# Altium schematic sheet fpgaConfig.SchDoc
size A; SheetNumber: 2; SheetTotal: 2
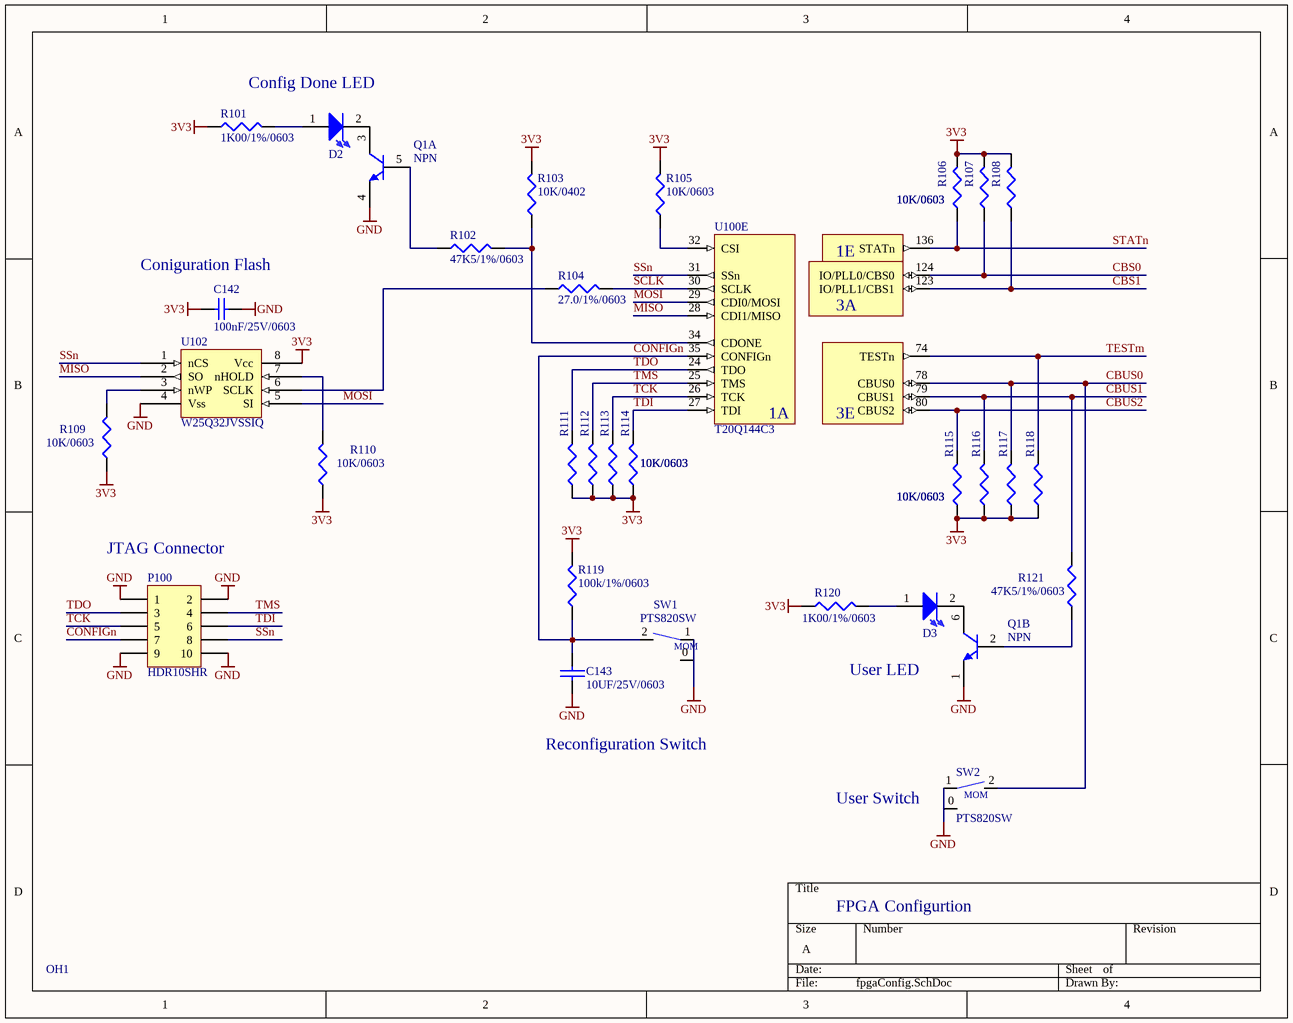
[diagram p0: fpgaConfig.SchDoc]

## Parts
C142  100nF/25V/0603  [MY0603]
C143  10UF/25V/0603  [MY0603]
D2  LTST-C191KGKT  [LED0603]  (value not drawn)
D3  LTST-C191KGKT  [LED0603]  (value not drawn)
OH1  OPENHW_SCH  (value not drawn)
P100  HDR10SHR  [HDR10]
Q1  NPN  [SC70-6_HAND]  (parts A,B of 2)
R101  1K00/1%/0603  [0603]
R102  47K5/1%/0603  [0603]
R103  10K/0402  [0402]
R104  27.0/1%/0603  [0603]
R105  10K/0603  [0603]
R106  10K/0603  [0603]
R107  10K/0603  [0603]
R108  10K/0603  [0603]
R109  10K/0603  [0603]
R110  10K/0603  [0603]
R111  10K/0603  [0603]
R112  10K/0603  [0603]
R113  10K/0603  [0603]
R114  10K/0603  [0603]
R115  10K/0603  [0603]
R116  10K/0603  [0603]
R117  10K/0603  [0603]
R118  10K/0603  [0603]
R119  100k/1%/0603  [0603]
R120  1K00/1%/0603  [0603]
R121  47K5/1%/0603  [0603]
SW1  PTS820SW  [PTS820]
SW2  PTS820SW  [PTS820]
U100  T20Q144C3  [LQFP144]  (part E of 6)
U102  W25Q32JVSSIQ  [so8w]

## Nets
3V3: C142.2 R101.1 R103.2 R105.2 R106.2 R107.2 R108.2 R109.1 R110.1 R111.1 R112.1 R113.1 R114.1 R115.1 R116.1 R117.1 R118.1 R119.2 R120.1 U102.8(Vcc)
GND: C142.1 C143.2 P100.1 P100.2 P100.9 P100.10 Q1.1 Q1.4 SW1.1 SW2.1 U102.4(Vss)
CBS0: R107.1 U100.124(IO/PLL0/CBS0)
CBS1: R108.1 U100.123(IO/PLL1/CBS1)
CBUS0: R117.2 SW2.2 U100.78(CBUS0)
CBUS1: R116.2 R121.2 U100.79(CBUS1)
CBUS2: R115.2 U100.80(CBUS2)
CONFIGn: C143.1 P100.7 R119.1 SW1.2 U100.35(CONFIGn)
MISO: U100.28(CDI1/MISO) U102.2(SO)
MOSI: U100.29(CDI0/MOSI) U102.5(SI)
SCLK: R104.2 U100.30(SCLK)
SSn: P100.8 U100.31(SSn) U102.1(nCS)
STATn: R106.1 U100.136(STATn)
TCK: P100.5 R113.2 U100.26(TCK)
TDI: P100.6 R114.2 U100.27(TDI)
TDO: P100.3 R111.2 U100.24(TDO)
TESTm: R118.2 U100.74(TESTn)
TMS: P100.4 R112.2 U100.25(TMS)
NetD2_1: D2.1(A) R101.2
NetD2_2: D2.2(K) Q1.3
NetD3_1: D3.1(A) R120.2
NetD3_2: D3.2(K) Q1.6
NetQ1_2: Q1.2 R121.1
NetQ1_5: Q1.5 R102.1
NetR102_2: R102.2 R103.1 U100.34(CDONE)
NetR104_1: R104.1 U102.6(SCLK)
NetR105_1: R105.1 U100.32(CSI)
NetR109_2: R109.2 U102.3(nWP)
NetR110_2: R110.2 U102.7(nHOLD)

Not connected (* = marked no-connect by the designer): SW1 0; SW2 0

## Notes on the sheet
- Config Done LED
- (near C142) Coniguration Flash
- (near P100) JTAG Connector
- User LED
- Reconfiguration Switch
- (near SW2) User Switch
- FPGA Configurtion

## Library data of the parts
C142 = CAP100NF25V: 0.1µF ±10% 25V Ceramic Capacitor X7R 0603 (1608 Metric); MFG PN: 06033C104KAT2A; DK PN: 478-3714-1-ND; MFG: AVX
C143 = 10UF/25V/0603: 10 µF ±20% 25V Ceramic Capacitor X5R 0603 (1608 Metric); MFG: Samsung; MFG PN: CL10A106MA8NRNC; DK PN: 1276-1869-1-ND
D2 D3 = LTST-C191KGKT: Green 571nm LED Indication - Discrete 2V 0603 (1608 Metric); DK PN: 160-1446-1-ND; MFG: Liteon
P100 = HDR10SHR: Connector Header Through Hole 10 position 0.100" (2.54mm); MFG: On Shore; MFG PN: 302-S101; DK PN: ED1543-ND
Q1 = MBT3904DW1T1G: Bipolar (BJT) Transistor Array 2 NPN (Dual) 40V 200mA 300MHz 150mW Surface Mount SC-88/SC70-6/SOT-363; MFG: On Semi; DK PN: MBT3904DW1T1GOSCT-ND
R101 R120 = 1K00/1%/0603: 1 kOhms ±1% 0.1W, 1/10W Chip Resistor 0603 (1608 Metric) Moisture Resistant Thick Film; MFG: Yeago; MFG PN: RC0603FR-071KL; DK PN: 311-1.00KHRCT-ND
R102 R121 = 47K5/1%/0603: 47.5 kOhms ±1% 0.1W, 1/10W Chip Resistor 0603 (1608 Metric) Moisture Resistant Thick Film; MFG: Yeago; MFG PN: RC0603FR-0747K5L; DK PN: 311-47.5KHRCT-ND
R103 = 10K/0402: 10 kOhms ±1% 0.063W, 1/16W Chip Resistor 0402 (1005 Metric) Automotive AEC-Q200, Moisture Resistant Thick Film; MFG: Yaego; MFG PN: AC0402FR-0710KL; DK PN: YAG3436CT-ND
R104 = 27.0/1%/0603: 27 Ohms ±1% 0.1W, 1/10W Chip Resistor 0603 (1608 Metric) Moisture Resistant Thick Film; MFG: Yeago; MFG PN: RC0603FR-0727RL; DK PN: 311-27.0HRCT-ND
R105-R118 = 10K/0603: RES 10.0K OHM 1/10W 1% 0603 SMD; MFG: Dale/Vishay; MFG PN: CRCW060310K0FKEA; DK PN: 541-10.0KHCT-ND
R119 = 100k/1%/0603: 100 kOhms ±1% 0.1W, 1/10W Chip Resistor 0603 (1608 Metric) Moisture Resistant Thick Film; MFG: Yeago; MFG PN: RC0603FR-07100KL; DK PN: 311-100KHRCT-ND
SW1 SW2 = PTS820SW: Tactile Switch SPST-NO Top Actuated Surface Mount; MFG: C&K; MFG PN: PTS820 J20M SMTR LFS; DK PN: CKN10505CT-ND
U100 = T20Q144C3: Trion® Field Programmable Gate Array (FPGA) IC 97 1044 19728 144-LQFP; MFG: Efinix; DK PN: 2134-T20Q144C3-ND
U102 = W25Q32JVSSIQ: FLASH - NOR Memory IC 32Mb (4M x 8) SPI - Quad I/O 133 MHz 8-SOIC; MFG: Winbond; MFG PN: W25Q32JVSSIQ TR; DK PN: W25Q32JVSSIQCT-ND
